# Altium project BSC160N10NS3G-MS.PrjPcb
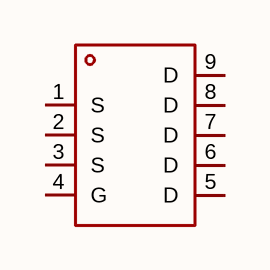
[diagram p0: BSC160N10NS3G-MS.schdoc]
1 sheet, 1 parts. Net scope: global (net labels, ports and power ports of the same name join across sheets).

## Sheet BSC160N10NS3G-MS.schdoc
size 127 x 101 mm

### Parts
Q?  bsc160n10ns3g-ms  [PDFN-8_L4.9-W5.8-P1.27-LS6.1-BL]  (value not drawn)

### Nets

Not connected (* = marked no-connect by the designer): Q? 1(S) 2(S) 3(S) 4(G) 5(D) 6(D) 7(D) 8(D) 9(D)

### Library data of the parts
Q? = bsc160n10ns3g-ms: 数量:1个N沟道;漏源电压(Vdss):100V;连续漏极电流(Id):-;导通电阻(RDS(on)):7.3mΩ@10V;耗散功率(Pd):97W;阈值电压(Vgs(th)):1.6V;; Manufacturer: MSKSEMI(美森科); AddInBom: yes; ModelId: 178189b27e7544aca50c111426555358; ModelName: PDFN-8_L4.9-W5.8-H1.0-P1.27; ModelTransform: 200.787,240.157,0,0,0,0,-0.097,0,0; Number: 1个N沟道; Drain to Source Voltage: 100V; Pd - Power Dissipation: 97W; Gate Threshold Voltage (Vgs(th)): 1.6V; Gate Charge(Qg): 39.4nC; Input Capacitance(Ciss): 2.046nF; Reverse Transfer Capacitance (Crss@Vds): 25pF; Type: N沟道; Output Capacitance(Coss): 865pF; Vgs: ±20V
